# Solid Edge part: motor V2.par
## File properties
Author: User
Template: normal.par
Last saved by: User
Revision: 31
Application: Solid Edge
Accuracy: 0.99
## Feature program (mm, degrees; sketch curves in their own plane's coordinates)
sketch for "unnamed RevolvedProtrusion 1" plane through (0, 0, 0) normal (1, 0, 0) x-axis (0, 1, 0)
  line (0, 52.1551) -> (-30, 52.1551)
  line (-30, 52.1551) -> (-30, 42.1551)
  line (-30, 42.1551) -> (-29, 42.1551)
  line (-29, 42.1551) -> (-29, 17.1551)
  line (-29, 17.1551) -> (-30, 17.1551)
  line (-30, 17.1551) -> (-30, 7.1551)
  line (-30, 7.1551) -> (0, 7.1551)
revolve "unnamed RevolvedProtrusion 1" add finite 360 deg about sketch line (0, 7.1551) -> (0, 52.1551)
fillet "unnamed Round 1"
thinwall "Thinwall_1"  Thickness = 1 mm
sketch for "ExtrudedProtrusion_4" plane through (0, 0, 17.1551) normal (0, 0, 1) x-axis (1, 0, 0)
  line (-6, 21.166) -> (-6, 34)
  arc centre (0, 34) radius 6 from (-6, 34) to (6, 34) cw
  line (6, 34) -> (6, 21.166)
  line (6, 21.166) -> (-6, 21.166)
extrude "ExtrudedProtrusion_4" add finite 18 along -normal
pattern "unnamed Pattern 1" of "ExtrudedProtrusion_4"
extrude "unnamed Protrusion 1" add finite 18
extrude "unnamed Protrusion 2" add finite 18
extrude "unnamed Protrusion 3" add finite 18
sketch for "unnamed Cutout 1" plane through (0, -30.583, -0.8449) normal (0, 0, -1) x-axis (1, 0, 0)
  circle centre (0, -30.583) radius 30
extrude "unnamed Cutout 1" cut to key point along -normal
fillet "Round_4" radius 5
fillet "Round_7" radius 5
fillet "Round_8" radius 5
sketch for "Hole_1" plane through (0, -34.6969, -0.8449) normal (0, 0, -1) x-axis (1, 0, 0)
  hole centre (0, -0.6969) bore radius 2.5
hole "Hole_1" diameter 5 finite
sketch for "unnamed Hole 1" plane through (0, -34.6969, -0.8449) normal (0, 0, -1) x-axis (1, 0, 0)
  hole centre (-34, -34.6969) bore radius 2.5
hole "unnamed Hole 1" finite
sketch for "unnamed Hole 2" plane through (0, -34.6969, -0.8449) normal (0, 0, -1) x-axis (1, 0, 0)
  hole centre (34, -34.6969) bore radius 2.5
hole "unnamed Hole 2" finite
sketch for "unnamed Hole 3" plane through (0, -34.6969, -0.8449) normal (0, 0, -1) x-axis (1, 0, 0)
  hole centre (0, -68.6969) bore radius 2.5
hole "unnamed Hole 3" finite
pattern "unnamed Pattern 2" of "Hole_1", "unnamed Hole 1", "unnamed Hole 2", "unnamed Hole 3"
sketch for "unnamed RevolvedProtrusion 2" plane through (0, 0, 0) normal (1, 0, 0) x-axis (0, 1, 0)
  line (0, -4.3449) -> (-2, -4.3449)
  line (-2, -4.3449) -> (-2, 5.6551)
  line (-2, 5.6551) -> (-8, 5.6551)
  line (-8, 5.6551) -> (-8, 53.6551)
  line (-8, 53.6551) -> (-2, 53.6551)
  line (-2, 53.6551) -> (-2, 63.6551)
  line (-2, 63.6551) -> (0, 63.6551)
revolve "unnamed RevolvedProtrusion 2" add full turn 360 deg about sketch line (0, 63.6551) -> (0, -4.3449)
sketch for "unnamed Cutout 2" plane through (0, 0, 7.1551) normal (0, 0, -1) x-axis (1, 0, 0)
  arc centre (0, 0) radius 10 from (-0.3724, 9.9931) to (0.3724, 9.9931) cw
  line (0.3724, 9.9931) -> (1.2445, 19.9612)
  arc centre (0, 0) radius 20 from (-1.2445, 19.9612) to (1.2445, 19.9612) cw
  line (-0.3724, 9.9931) -> (-1.2445, 19.9612)
extrude "unnamed Cutout 2" cut through along -normal
pattern "unnamed Pattern 3" of "unnamed Cutout 2"
extrude "unnamed Cutout 3" cut through
extrude "unnamed Cutout 4" cut through
extrude "unnamed Cutout 5" cut through
extrude "unnamed Cutout 6" cut through
extrude "unnamed Cutout 7" cut through
extrude "unnamed Cutout 8" cut through
extrude "unnamed Cutout 9" cut through
extrude "unnamed Cutout 10" cut through
extrude "unnamed Cutout 11" cut through
extrude "unnamed Cutout 12" cut through
extrude "unnamed Cutout 13" cut through
extrude "unnamed Cutout 14" cut through
extrude "unnamed Cutout 15" cut through
extrude "unnamed Cutout 16" cut through
extrude "unnamed Cutout 17" cut through
extrude "unnamed Cutout 18" cut through
extrude "unnamed Cutout 19" cut through
extrude "unnamed Cutout 20" cut through
extrude "unnamed Cutout 21" cut through
extrude "unnamed Cutout 22" cut through
extrude "unnamed Cutout 23" cut through
extrude "unnamed Cutout 24" cut through
extrude "unnamed Cutout 25" cut through
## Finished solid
Body 1: solid body, 318 faces, 868 edges, 554 vertices.
  Faces by surface: plane 139, cylinder 129, blend 32, torus 18
  Edges by curve: line 471, circle 306, intersection 91
Bounding box of the edges (mm; curved faces can reach further): 80.000 x 80.000 x 53.000, from (-40, -40, -0.8449) to (40, 40, 52.1551).
Cylindrical faces by radius (mm): R2.5 x4, R5 x9, R6 x4, R10 x48, R20 x48, R28 x1, R29 x6, R30 x9
Toroidal faces (ring radius, tube radius in mm): R1 r5 x4, R22 r7 x5, R22 r8 x5, R25 r5 x4
Planar faces by outward normal: +x 5, +y 5, +z 8, -x 5, -y 5, -z 15, oblique 96
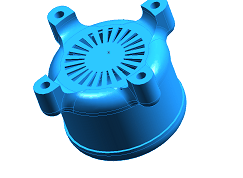
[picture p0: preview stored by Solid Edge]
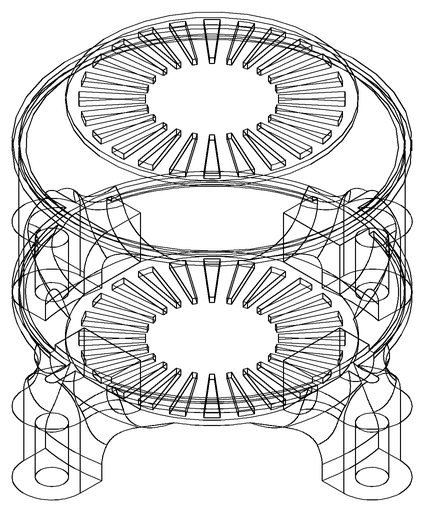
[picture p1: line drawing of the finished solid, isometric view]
